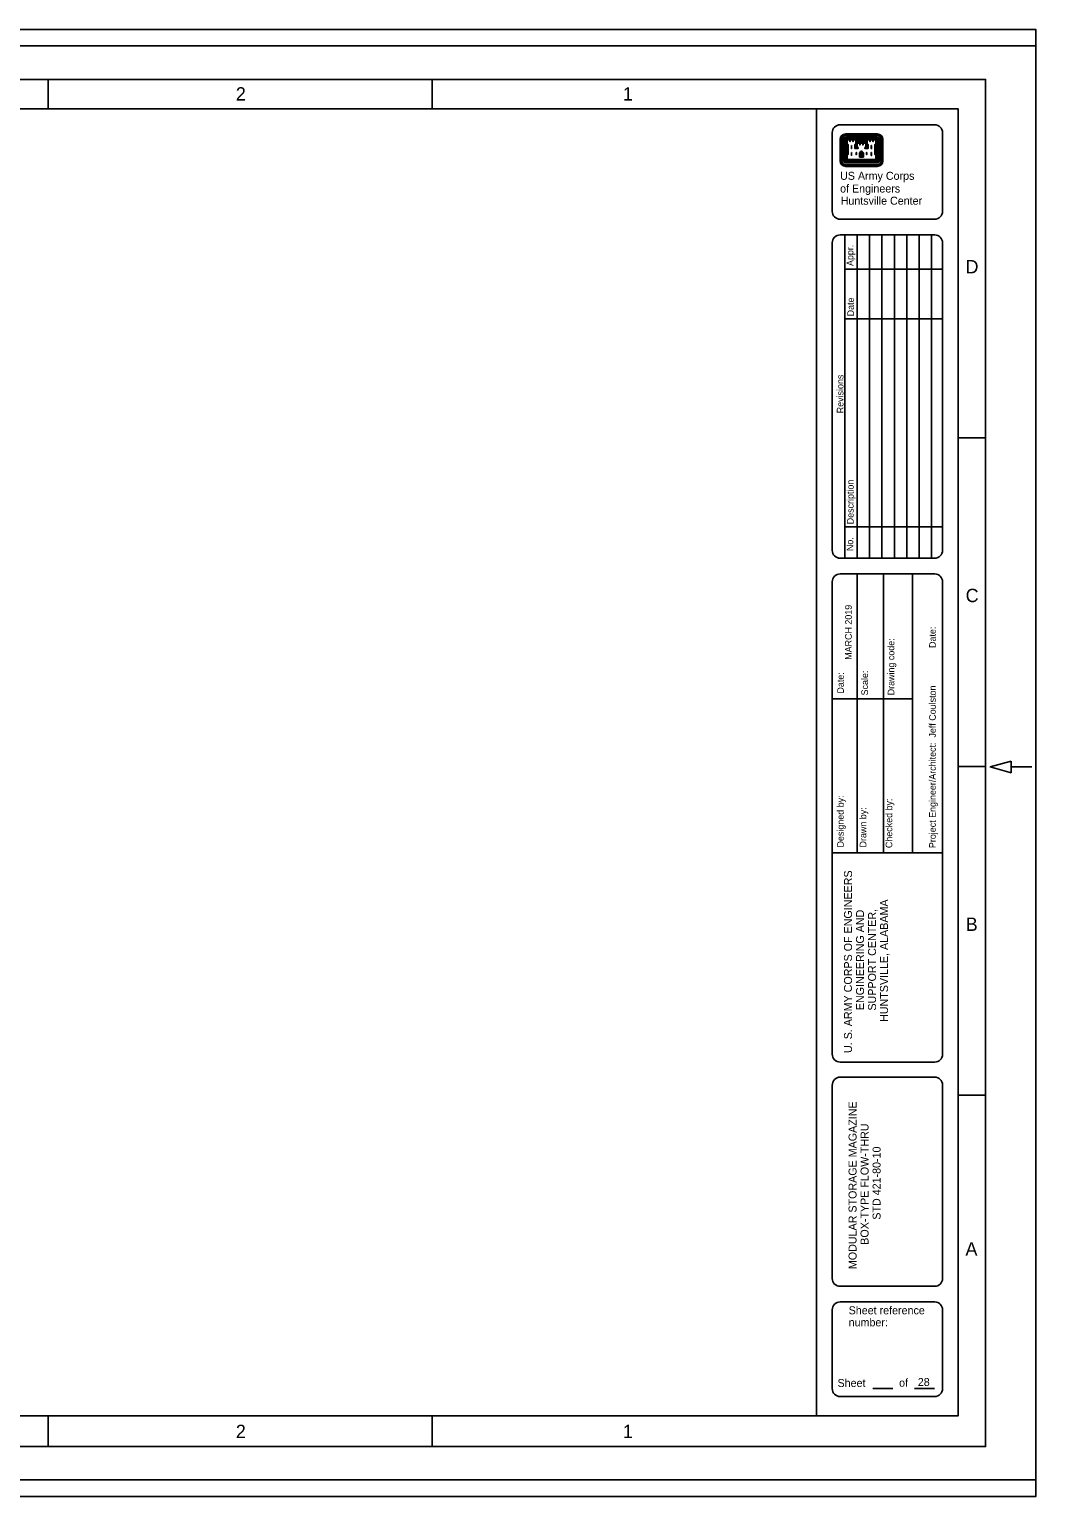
# Model space of a CAD drawing. Extents: x -0.04 to 2.79, y -0.02 to 1.81.
# Drawn here: x 1.534 to 2.792, y -0.021 to 1.813 of the extents above; entities that cross this region are included whole.
import ezdxf

# ---------------------------------------------------------------- set-up
doc = ezdxf.new("R2010")
doc.units = 0
for name, color, linetype in [('G-ANNO-NPLT', 7, 'Continuous'), ('G-ANNO-PLOT', 7, 'Continuous'), ('G-ANNO-TTLB', 7, 'Continuous')]:
    doc.layers.add(name, color=color, linetype=linetype)

msp = doc.modelspace()

# ---------------------------------------------------------------- linework, layer by layer
at = {"layer": 'G-ANNO-NPLT'}
msp.add_lwpolyline([(-0.0417, 1.8125), (2.7917, 1.8125), (2.7917, -0.0208), (-0.0417, -0.0208)], close=True, dxfattribs=at)
at = {"layer": 'G-ANNO-PLOT'}
for p, q in [((2.7917, 1.8125), (-0.0417, 1.8125)), ((2.7917, 1.8125), (2.7917, -0.0208)), ((2.7917, -0.0208), (-0.0417, -0.0208))]:
    msp.add_line(p, q, dxfattribs=at)
msp.add_lwpolyline([(0, 0), (2.7917, 0), (2.7917, 1.7917), (0, 1.7917)], close=True, dxfattribs=at)
at = {"layer": 'G-ANNO-TTLB'}
for p, q in [((1.5578, 1.7131), (1.5578, 1.75)), ((2.0378, 1.7131), (2.0378, 1.75)), ((2.5178, 0.0803), (2.5178, 1.7131)), ((2.5473, 1.6749), (2.5473, 1.6483)), ((2.5477, 1.6749), (2.5477, 1.6483)), ((2.5484, 1.6749), (2.5484, 1.6483)), ((2.5489, 1.6749), (2.5489, 1.6483)), ((2.5494, 1.6749), (2.5494, 1.6483)), ((2.5517, 1.6749), (2.5517, 1.6483)), ((2.5523, 1.6749), (2.5523, 1.6483)), ((2.5528, 1.6749), (2.5528, 1.6483)), ((2.5534, 1.6749), (2.5534, 1.6483)), ((2.554, 1.6749), (2.554, 1.6483)), ((2.5938, 1.6819), (2.5543, 1.6819)), ((2.5938, 1.6815), (2.5543, 1.6815)), ((2.5938, 1.6809), (2.5543, 1.6809)), ((2.5938, 1.6804), (2.5543, 1.6804)), ((2.5938, 1.6798), (2.5543, 1.6798)), ((2.5938, 1.6776), (2.5543, 1.6776)), ((2.5938, 1.677), (2.5543, 1.677)), ((2.5938, 1.6764), (2.5543, 1.6764)), ((2.5938, 1.6758), (2.5543, 1.6758)), ((2.5938, 1.6753), (2.5543, 1.6753)), ((2.5545, 1.6749), (2.5545, 1.6484)), ((2.5551, 1.6749), (2.5551, 1.649)), ((2.5555, 1.6692), (2.5555, 1.6556)), ((2.5561, 1.6686), (2.5561, 1.6563)), ((2.5679, 1.6747), (2.5801, 1.6747)), ((2.5679, 1.6742), (2.5801, 1.6742)), ((2.5679, 1.6737), (2.5801, 1.6737)), ((2.5679, 1.6731), (2.5801, 1.6731)), ((2.5679, 1.6725), (2.5801, 1.6725)), ((2.5679, 1.672), (2.5801, 1.672)), ((2.5679, 1.6714), (2.5801, 1.6714)), ((2.592, 1.6686), (2.592, 1.6563)), ((2.5925, 1.6692), (2.5925, 1.6557)), ((2.593, 1.6749), (2.593, 1.649)), ((2.5935, 1.6749), (2.5935, 1.6484)), ((2.5941, 1.6749), (2.5941, 1.6483)), ((2.5947, 1.6749), (2.5947, 1.6483)), ((2.5953, 1.6749), (2.5953, 1.6483)), ((2.5958, 1.6749), (2.5958, 1.6483)), ((2.5964, 1.6749), (2.5964, 1.6483)), ((2.5986, 1.6749), (2.5986, 1.6483)), ((2.5992, 1.6749), (2.5992, 1.6483)), ((2.5997, 1.6749), (2.5997, 1.6483)), ((2.6003, 1.6749), (2.6003, 1.6483)), ((2.6007, 1.6749), (2.6007, 1.6483)), ((2.5714, 1.6528), (2.5714, 1.6572)), ((2.5714, 1.6528), (2.5767, 1.6528)), ((2.5719, 1.6528), (2.5719, 1.6572)), ((2.5725, 1.6528), (2.5725, 1.6572)), ((2.5731, 1.6528), (2.5731, 1.6572)), ((2.5737, 1.6528), (2.5737, 1.6572)), ((2.5744, 1.6528), (2.5744, 1.6572)), ((2.575, 1.6528), (2.575, 1.6572)), ((2.5755, 1.6528), (2.5755, 1.6572)), ((2.5761, 1.6528), (2.5761, 1.6572)), ((2.5767, 1.6528), (2.5767, 1.6572)), ((2.5938, 1.6478), (2.5543, 1.6478)), ((2.5938, 1.6473), (2.5543, 1.6473)), ((2.5938, 1.6467), (2.5543, 1.6467)), ((2.5938, 1.6462), (2.5543, 1.6462)), ((2.5938, 1.6456), (2.5543, 1.6456)), ((2.5938, 1.6433), (2.5543, 1.6433)), ((2.5938, 1.6428), (2.5543, 1.6428)), ((2.5938, 1.6423), (2.5543, 1.6423)), ((2.5938, 1.6417), (2.5543, 1.6417)), ((2.5938, 1.6412), (2.5543, 1.6412)), ((2.5935, 1.6484), (2.5545, 1.6484)), ((2.593, 1.649), (2.5551, 1.649)), ((2.5532, 1.5557), (2.5532, 1.1517)), ((2.5686, 1.5557), (2.5686, 1.1517)), ((2.5842, 1.5557), (2.5842, 1.1517)), ((2.5996, 1.5557), (2.5996, 1.1517)), ((2.6151, 1.5557), (2.6151, 1.1517)), ((2.6306, 1.5557), (2.6306, 1.1517)), ((2.646, 1.5557), (2.646, 1.1517)), ((2.6615, 1.5557), (2.6615, 1.1517)), ((2.5532, 1.513), (2.6754, 1.513)), ((2.5532, 1.4507), (2.6754, 1.4507)), ((2.695, 1.3022), (2.7292, 1.3022)), ((2.5532, 1.1911), (2.6754, 1.1911)), ((2.5685, 1.1321), (2.5685, 0.976)), ((2.6014, 1.1321), (2.6014, 0.976)), ((2.6377, 1.1321), (2.6377, 0.7837)), ((2.6377, 0.976), (2.5376, 0.976)), ((2.5685, 0.976), (2.5685, 0.7837)), ((2.6014, 0.976), (2.6014, 0.7837)), ((2.695, 0.8914), (2.7292, 0.8914)), ((2.7609, 0.891), (2.787, 0.891)), ((2.6754, 0.7837), (2.5376, 0.7837)), ((2.5474, 0.5221), (2.6655, 0.5221)), ((2.695, 0.4806), (2.7292, 0.4806)), ((2.5883, 0.1141), (2.6134, 0.1141)), ((2.6403, 0.1141), (2.6654, 0.1141)), ((1.5578, 0.0418), (1.5578, 0.0803)), ((2.0378, 0.0418), (2.0378, 0.0803))]:
    msp.add_line(p, q, dxfattribs=at)
for points in [[(0.0833, 0.0417), (2.7292, 0.0417), (2.7292, 1.75), (0.2515, 1.75)], [(0.1166, 0.0803), (2.695, 0.0803), (2.695, 1.7131), (0.1166, 1.7131)], [(2.5474, 1.6934), (2.6655, 1.6934)], [(2.5376, 1.5851), (2.5376, 1.6835)], [(2.5555, 1.6749), (2.5555, 1.6698), (2.5567, 1.6686), (2.5567, 1.6563), (2.5555, 1.6551), (2.5555, 1.6494), (2.5926, 1.6494), (2.5926, 1.6551), (2.5914, 1.6563), (2.5914, 1.6686), (2.5926, 1.6698), (2.5926, 1.6749), (2.5877, 1.6749), (2.5839, 1.6749), (2.5804, 1.6749), (2.5804, 1.6698), (2.5817, 1.6686), (2.5817, 1.6642), (2.5789, 1.6642), (2.5789, 1.6646), (2.5801, 1.6657), (2.5801, 1.6708), (2.5752, 1.6708), (2.5714, 1.6708), (2.5679, 1.6708), (2.5679, 1.6657), (2.5691, 1.6646), (2.5691, 1.6642), (2.5664, 1.6642), (2.5664, 1.6686), (2.5676, 1.6698), (2.5676, 1.6749), (2.5626, 1.6749), (2.5589, 1.6749), (2.5555, 1.6749)], [(2.5561, 1.6743), (2.5561, 1.67), (2.5573, 1.6688), (2.5573, 1.656), (2.5561, 1.6549), (2.5561, 1.65), (2.592, 1.65), (2.592, 1.6549), (2.5909, 1.656), (2.5909, 1.6688), (2.592, 1.67), (2.592, 1.6743), (2.5886, 1.6743), (2.5886, 1.6723), (2.5883, 1.6723), (2.5883, 1.6743), (2.5848, 1.6743), (2.5848, 1.6723), (2.5845, 1.6723), (2.5845, 1.6743), (2.581, 1.6743), (2.581, 1.67), (2.5822, 1.6688), (2.5822, 1.6636), (2.5784, 1.6636), (2.5784, 1.6648), (2.5796, 1.6659), (2.5796, 1.6703), (2.5761, 1.6703), (2.5761, 1.6682), (2.5757, 1.6682), (2.5757, 1.6703), (2.5723, 1.6703), (2.5723, 1.6682), (2.5719, 1.6682), (2.5719, 1.6703), (2.5685, 1.6703), (2.5685, 1.6659), (2.5697, 1.6648), (2.5697, 1.6636), (2.5658, 1.6636), (2.5658, 1.6688), (2.5671, 1.67), (2.5671, 1.6743), (2.5636, 1.6743), (2.5636, 1.6723), (2.5633, 1.6723), (2.5633, 1.6743), (2.5598, 1.6743), (2.5598, 1.6723), (2.5595, 1.6723), (2.5595, 1.6743), (2.5561, 1.6743)], [(2.5673, 1.6687), (2.567, 1.6684), (2.567, 1.6647), (2.5682, 1.6647), (2.5674, 1.6655), (2.5674, 1.6688)], [(2.5807, 1.6687), (2.581, 1.6684), (2.581, 1.6647), (2.5799, 1.6647), (2.5807, 1.6655), (2.5807, 1.6688)], [(2.6754, 1.6835), (2.6754, 1.5851)], [(2.5614, 1.6674), (2.5614, 1.6636), (2.5617, 1.6636), (2.5617, 1.6674), (2.5614, 1.6674)], [(2.5614, 1.6587), (2.5614, 1.6549), (2.5617, 1.6549), (2.5617, 1.6587), (2.5614, 1.6587)], [(2.5673, 1.6587), (2.5673, 1.6561), (2.5677, 1.6561), (2.5677, 1.6587), (2.5673, 1.6587)], [(2.5807, 1.6587), (2.5807, 1.6561), (2.5804, 1.6561), (2.5804, 1.6587), (2.5807, 1.6587)], [(2.5867, 1.6674), (2.5867, 1.6636), (2.5863, 1.6636), (2.5863, 1.6674), (2.5867, 1.6674)], [(2.5867, 1.6587), (2.5867, 1.6549), (2.5863, 1.6549), (2.5863, 1.6587), (2.5867, 1.6587)], [(2.6655, 1.5753), (2.5474, 1.5753)], [(2.5376, 1.5458), (2.5376, 1.1615)], [(2.6655, 1.5557), (2.5474, 1.5557)], [(2.6754, 1.1615), (2.6754, 1.5458)], [(2.5474, 1.1517), (2.6655, 1.1517)], [(2.5376, 1.1223), (2.5376, 0.5321)], [(2.6655, 1.1321), (2.5474, 1.1321)], [(2.6754, 0.5319), (2.6754, 1.1223)], [(2.6655, 0.5033), (2.5474, 0.5033)], [(2.5376, 0.493), (2.5376, 0.2518)], [(2.6754, 0.2518), (2.6754, 0.4935)], [(2.5474, 0.242), (2.6655, 0.242)], [(2.5474, 0.2224), (2.6655, 0.2224)], [(2.5376, 0.1141), (2.5376, 0.2126)], [(2.6754, 0.2126), (2.6754, 0.1141)], [(2.6655, 0.1043), (2.5474, 0.1043)]]:
    msp.add_lwpolyline(points, dxfattribs=at)
msp.add_lwpolyline([(2.7609, 0.8983), (2.735, 0.891), (2.7609, 0.8837)], close=True, dxfattribs=at)
for centre, major_axis, start_param, end_param in [((2.5474, 1.6835), (-0.00984, 0), 4.712389, 6.283185), ((2.6655, 1.6835), (-0.00984, 0), 3.141593, 4.712389), ((2.5543, 1.6749), (-0.00696, 0), 4.712389, 6.283185), ((2.5543, 1.6749), (-0.00656, 0), 4.712389, 6.283185), ((2.5543, 1.6749), (-0.006, 0), 4.712389, 6.283185), ((2.5543, 1.6749), (-0.00543, 0), 4.712389, 6.283185), ((2.5543, 1.6749), (-0.00487, 0), 4.712389, 6.283185), ((2.5543, 1.6749), (-0.00261, 0), 4.712389, 6.283185), ((2.5543, 1.6749), (-0.00205, 0), 4.712389, 6.283185), ((2.5543, 1.6749), (-0.00148, 0), 4.712389, 6.283185), ((2.5543, 1.6749), (0.000919, 0), 1.570796, 3.141593), ((2.5543, 1.6749), (-0.000355, 0), 4.712389, 6.283185), ((2.5938, 1.6749), (-0.00696, 0), 3.141593, 4.712389), ((2.5938, 1.6749), (0.00656, 0), 0, 1.570796), ((2.5938, 1.6749), (0.006, 0), 0, 1.570796), ((2.5938, 1.6749), (0.00543, 0), 0, 1.570796), ((2.5938, 1.6749), (0.00487, 0), 0, 1.570796), ((2.5938, 1.6749), (-0.00261, 0), 3.141593, 4.712389), ((2.5938, 1.6749), (-0.00205, 0), 3.141593, 4.712389), ((2.5938, 1.6749), (-0.00148, 0), 3.141593, 4.712389), ((2.5938, 1.6749), (-0.000919, 0), 3.141593, 4.712389), ((2.5938, 1.6749), (-0.000355, 0), 3.141593, 4.712389), ((2.575, 1.6569), (0.00361, 0), 1.844255, 3.072783), ((2.575, 1.6569), (-0.00304, 0), 4.947481, 6.214375), ((2.575, 1.6569), (-0.00248, 0), 4.947481, 6.214375), ((2.575, 1.6569), (-0.00192, 0), 4.947481, 6.214375), ((2.5731, 1.6569), (0.00135, 0), 0.06881, 1.335704), ((2.5731, 1.6569), (0.00192, 0), 0.06881, 1.335704), ((2.5731, 1.6569), (-0.00248, 0), 3.210403, 4.477297), ((2.575, 1.6569), (-0.00135, 0), 4.947481, 6.214375), ((2.5731, 1.6569), (0.00304, 0), 0.06881, 1.335704), ((2.5731, 1.6569), (0.00361, 0), 0.06881, 1.298435), ((2.5543, 1.6482), (0.00696, 0), 3.141593, 4.712389), ((2.5543, 1.6482), (0.00656, 0), 3.141593, 4.712389), ((2.5543, 1.6482), (-0.006, 0), 0, 1.570796), ((2.5543, 1.6482), (0.00543, 0), 3.141593, 4.712389), ((2.5543, 1.6482), (0.00487, 0), 3.141593, 4.712389), ((2.5543, 1.6482), (0.00261, 0), 3.141593, 4.712389), ((2.5543, 1.6482), (0.00205, 0), 3.141593, 4.712389), ((2.5543, 1.6482), (0.00148, 0), 3.141593, 4.712389), ((2.5543, 1.6482), (0.000919, 0), 3.141593, 4.712389), ((2.5543, 1.6482), (0.000355, 0), 3.141593, 4.712389), ((2.5938, 1.6482), (0.00696, 0), 4.712389, 6.283185), ((2.5938, 1.6482), (0.00261, 0), 4.712389, 6.283185), ((2.5938, 1.6482), (0.00205, 0), 4.712389, 6.283185), ((2.5938, 1.6482), (0.00148, 0), 4.712389, 6.283185), ((2.5938, 1.6482), (0.000919, 0), 4.712389, 6.283185), ((2.5938, 1.6482), (0.000355, 0), 4.712389, 6.283185), ((2.5938, 1.6482), (0.00487, 0), 4.712389, 6.283185), ((2.5938, 1.6482), (0.00543, 0), 4.712389, 6.283185), ((2.5938, 1.6482), (0.006, 0), 4.712389, 6.283185), ((2.5938, 1.6482), (0.00656, 0), 4.712389, 6.283185), ((2.5474, 1.5851), (-0.00984, 0), 0, 1.570796), ((2.6655, 1.5851), (0.00984, 0), 4.712389, 6.283185), ((2.5474, 1.5458), (-0.00984, 0), 4.712389, 6.281588), ((2.6655, 1.5458), (-0.00984, 0), 3.141593, 4.712389), ((2.5474, 1.1615), (-0.00984, 0), 0, 1.570796), ((2.6655, 1.1615), (0.00984, 0), 4.712389, 6.283185), ((2.5474, 1.1223), (-0.00984, 0), 4.712389, 6.283185), ((2.6655, 1.1223), (-0.00984, 0), 3.141593, 4.712389), ((2.5474, 0.5319), (-0.00984, 0), 6.267222, 7.853982), ((2.6655, 0.5319), (0.00984, 0), 4.712389, 6.283185), ((2.5474, 0.4935), (-0.00984, 0), 4.712389, 6.327939), ((2.6655, 0.4935), (0.00984, 0), 0, 1.570796), ((2.5474, 0.2518), (-0.00984, 0), 0, 1.570796), ((2.6655, 0.2518), (0.00984, 0), 4.712389, 6.283185), ((2.5474, 0.2126), (-0.00984, 0), 4.712389, 6.283185), ((2.6655, 0.2126), (0.00984, 0), 0, 1.570796), ((2.5474, 0.1141), (-0.00984, 0), 0, 1.570796), ((2.6655, 0.1141), (0.00984, 0), 4.712389, 6.283185)]:
    msp.add_ellipse(centre, major_axis=major_axis, ratio=0.999936, start_param=start_param, end_param=end_param, dxfattribs=at)

# ---------------------------------------------------------------- texts
for s, height, p in [('2', 0.0167, (1.7923, 1.7235)), ('1', 0.0167, (2.2759, 1.7235)), ('US Army Corps', 0.01, (2.5473, 1.6245)), ('of Engineers', 0.01, (2.5473, 1.6086)), ('Huntsville Center', 0.01, (2.548, 1.5934)), ('D', 0.0167, (2.7041, 1.5076)), ('D', 0.0167, (2.7041, 1.5076)), ('C', 0.0167, (2.7042, 1.0968)), ('B', 0.0167, (2.7043, 0.686)), ('A', 0.0167, (2.704, 0.2804)), ('Sheet reference', 0.01, (2.558, 0.207)), ('number:', 0.01, (2.558, 0.192)), ('Sheet', 0.01, (2.5441, 0.1162)), ('of', 0.01, (2.621, 0.1165)), ('28', 0.01, (2.6444, 0.1174)), ('2', 0.0167, (1.7923, 0.0523)), ('1', 0.0167, (2.2759, 0.0523))]:
    msp.add_text(s, height=height, dxfattribs=at).set_placement(p)
for s, height, p in [('Appr.', 0.00833, (2.5639, 1.5168)), ('Date', 0.00833, (2.5646, 1.4539)), ('Revisions', 0.00833, (2.5515, 1.3328)), ('Description', 0.008333, (2.5642, 1.1941)), ('No.', 0.00833, (2.5637, 1.1606)), ('MARCH 2019', 0.00833, (2.5619, 1.0248)), ('Date:', 0.00833, (2.6669, 1.0396)), ('Drawing code:', 0.008333, (2.6151, 0.9804)), ('Scale:', 0.00833, (2.5822, 0.9803)), ('Date:', 0.00833, (2.552, 0.9826)), ('Project Engineer/Architect:  Jeff Coulston', 0.008333, (2.6669, 0.7895)), ('Designed by:', 0.008333, (2.5519, 0.7903)), ('Checked by:', 0.008333, (2.6125, 0.7895)), ('Drawn by:', 0.00833, (2.5801, 0.7903)), ('U. S. ARMY CORPS OF ENGINEERS', 0.01, (2.5622, 0.5335)), ('HUNTSVILLE, ALABAMA', 0.01, (2.6072, 0.5723)), ('ENGINEERING AND', 0.01, (2.5772, 0.587)), ('SUPPORT CENTER,', 0.01, (2.5922, 0.5865)), ('MODULAR STORAGE MAGAZINE', 0.01, (2.5679, 0.2635)), ('BOX-TYPE FLOW-THRU', 0.01, (2.5829, 0.2939)), ('STD 421-80-10', 0.01, (2.5979, 0.3252))]:
    msp.add_text(s, height=height, rotation=90, dxfattribs=at).set_placement(p)

doc.saveas('drawing.dxf')
